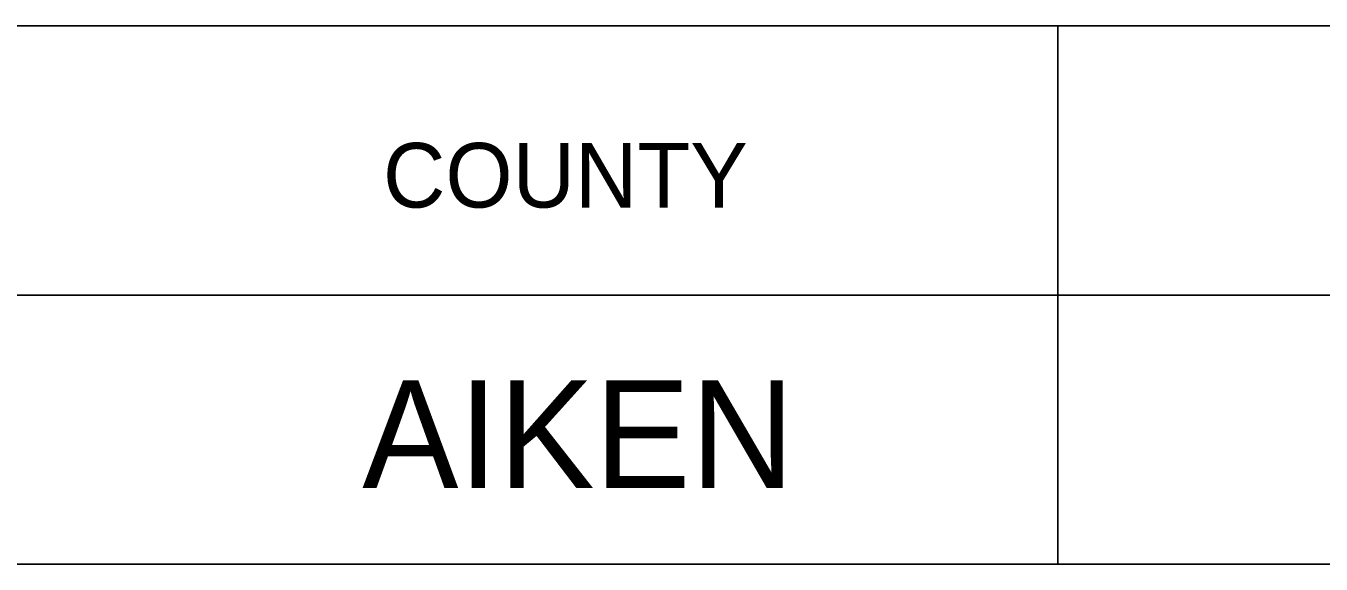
# Model space of a CAD drawing. Extents: x 1000 to 1162, y 999 to 8520.
# Drawn here: x 1139.21 to 1145.22, y 6850.05 to 6852.55 of the extents above; entities that cross this region are included whole.
import ezdxf

# ---------------------------------------------------------------- set-up
doc = ezdxf.new("R2010")
doc.units = 0
doc.layers.add('Level 20', color=7, linetype='Continuous')
doc.layers.add('Level 3', color=7, linetype='Continuous')

msp = doc.modelspace()

# ---------------------------------------------------------------- linework, layer by layer
at = {"layer": 'Level 3'}
for p, q in [((1133.055, 6852.5458), (1161.555, 6852.5458)), ((1133.055, 6852.5458), (1161.555, 6852.5458)), ((1133.055, 6852.5458), (1161.555, 6852.5458)), ((1133.055, 6852.5458), (1161.555, 6852.5458)), ((1133.055, 6852.5458), (1161.555, 6852.5458)), ((1133.055, 6852.5458), (1161.555, 6852.5458)), ((1133.055, 6852.5458), (1161.555, 6852.5458)), ((1133.055, 6852.5458), (1161.555, 6852.5458)), ((1133.055, 6852.5458), (1161.555, 6852.5458)), ((1133.055, 6852.5458), (1161.555, 6852.5458)), ((1133.055, 6852.5458), (1161.555, 6852.5458)), ((1133.055, 6852.5458), (1161.555, 6852.5458)), ((1133.055, 6852.5458), (1161.555, 6852.5458)), ((1133.055, 6852.5458), (1161.555, 6852.5458)), ((1133.055, 6852.5458), (1161.555, 6852.5458)), ((1133.055, 6852.5458), (1161.555, 6852.5458)), ((1133.055, 6852.5458), (1161.555, 6852.5458)), ((1133.055, 6852.5458), (1161.555, 6852.5458)), ((1133.055, 6852.5458), (1161.555, 6852.5458)), ((1133.055, 6852.5458), (1161.555, 6852.5458)), ((1133.055, 6852.5458), (1161.555, 6852.5458)), ((1133.055, 6852.5458), (1161.555, 6852.5458)), ((1133.055, 6852.5458), (1161.555, 6852.5458)), ((1133.055, 6852.5458), (1161.555, 6852.5458)), ((1133.055, 6852.5458), (1161.555, 6852.5458)), ((1133.055, 6852.5458), (1161.555, 6852.5458)), ((1133.055, 6852.5458), (1161.555, 6852.5458)), ((1133.055, 6852.5458), (1161.555, 6852.5458)), ((1133.055, 6852.5458), (1161.555, 6852.5458)), ((1133.055, 6852.5458), (1161.555, 6852.5458)), ((1133.055, 6852.5458), (1161.555, 6852.5458)), ((1133.055, 6852.5458), (1161.555, 6852.5458)), ((1133.055, 6852.5458), (1161.555, 6852.5458)), ((1133.055, 6852.5458), (1161.555, 6852.5458)), ((1133.055, 6852.5458), (1161.555, 6852.5458)), ((1133.055, 6852.5458), (1161.555, 6852.5458)), ((1133.055, 6852.5458), (1161.555, 6852.5458)), ((1133.055, 6852.5458), (1161.555, 6852.5458)), ((1133.055, 6852.5458), (1161.555, 6852.5458)), ((1133.055, 6852.5458), (1161.555, 6852.5458)), ((1133.055, 6852.5458), (1161.555, 6852.5458)), ((1133.055, 6852.5458), (1161.555, 6852.5458)), ((1133.055, 6852.5458), (1161.555, 6852.5458)), ((1133.055, 6852.5458), (1161.555, 6852.5458)), ((1133.055, 6852.5458), (1161.555, 6852.5458)), ((1133.055, 6852.5458), (1161.555, 6852.5458)), ((1133.055, 6852.5458), (1161.555, 6852.5458)), ((1133.055, 6852.5458), (1161.555, 6852.5458)), ((1133.055, 6852.5458), (1161.555, 6852.5458)), ((1143.9997, 6852.5458), (1143.9997, 6850.0458)), ((1143.9997, 6852.5458), (1143.9997, 6850.0458)), ((1143.9997, 6852.5458), (1143.9997, 6850.0458)), ((1143.9997, 6852.5458), (1143.9997, 6850.0458)), ((1143.9997, 6852.5458), (1143.9997, 6850.0458)), ((1143.9997, 6852.5458), (1143.9997, 6850.0458)), ((1143.9997, 6852.5458), (1143.9997, 6850.0458)), ((1143.9997, 6852.5458), (1143.9997, 6850.0458)), ((1143.9997, 6852.5458), (1143.9997, 6850.0458)), ((1143.9997, 6852.5458), (1143.9997, 6850.0458)), ((1143.9997, 6852.5458), (1143.9997, 6850.0458)), ((1143.9997, 6852.5458), (1143.9997, 6850.0458)), ((1143.9997, 6852.5458), (1143.9997, 6850.0458)), ((1143.9997, 6852.5458), (1143.9997, 6850.0458)), ((1143.9997, 6852.5458), (1143.9997, 6850.0458)), ((1143.9997, 6852.5458), (1143.9997, 6850.0458)), ((1143.9997, 6852.5458), (1143.9997, 6850.0458)), ((1143.9997, 6852.5458), (1143.9997, 6850.0458)), ((1143.9997, 6852.5458), (1143.9997, 6850.0458)), ((1143.9997, 6852.5458), (1143.9997, 6850.0458)), ((1143.9997, 6852.5458), (1143.9997, 6850.0458)), ((1143.9997, 6852.5458), (1143.9997, 6850.0458)), ((1143.9997, 6852.5458), (1143.9997, 6850.0458)), ((1143.9997, 6852.5458), (1143.9997, 6850.0458)), ((1143.9997, 6852.5458), (1143.9997, 6850.0458)), ((1143.9997, 6852.5458), (1143.9997, 6850.0458)), ((1143.9997, 6852.5458), (1143.9997, 6850.0458)), ((1143.9997, 6852.5458), (1143.9997, 6850.0458)), ((1143.9997, 6852.5458), (1143.9997, 6850.0458)), ((1143.9997, 6852.5458), (1143.9997, 6850.0458)), ((1143.9997, 6852.5458), (1143.9997, 6850.0458)), ((1143.9997, 6852.5458), (1143.9997, 6850.0458)), ((1143.9997, 6852.5458), (1143.9997, 6850.0458)), ((1143.9997, 6852.5458), (1143.9997, 6850.0458)), ((1143.9997, 6852.5458), (1143.9997, 6850.0458)), ((1143.9997, 6852.5458), (1143.9997, 6850.0458)), ((1143.9997, 6852.5458), (1143.9997, 6850.0458)), ((1143.9997, 6852.5458), (1143.9997, 6850.0458)), ((1143.9997, 6852.5458), (1143.9997, 6850.0458)), ((1143.9997, 6852.5458), (1143.9997, 6850.0458)), ((1143.9997, 6852.5458), (1143.9997, 6850.0458)), ((1143.9997, 6852.5458), (1143.9997, 6850.0458)), ((1143.9997, 6852.5458), (1143.9997, 6850.0458)), ((1143.9997, 6852.5458), (1143.9997, 6850.0458)), ((1143.9997, 6852.5458), (1143.9997, 6850.0458)), ((1143.9997, 6852.5458), (1143.9997, 6850.0458)), ((1143.9997, 6852.5458), (1143.9997, 6850.0458)), ((1143.9997, 6852.5458), (1143.9997, 6850.0458)), ((1143.9997, 6852.5458), (1143.9997, 6850.0458)), ((1133.055, 6851.2958), (1161.555, 6851.2958)), ((1133.055, 6851.2958), (1161.555, 6851.2958)), ((1133.055, 6851.2958), (1161.555, 6851.2958)), ((1133.055, 6851.2958), (1161.555, 6851.2958)), ((1133.055, 6851.2958), (1161.555, 6851.2958)), ((1133.055, 6851.2958), (1161.555, 6851.2958)), ((1133.055, 6851.2958), (1161.555, 6851.2958)), ((1133.055, 6851.2958), (1161.555, 6851.2958)), ((1133.055, 6851.2958), (1161.555, 6851.2958)), ((1133.055, 6851.2958), (1161.555, 6851.2958)), ((1133.055, 6851.2958), (1161.555, 6851.2958)), ((1133.055, 6851.2958), (1161.555, 6851.2958)), ((1133.055, 6851.2958), (1161.555, 6851.2958)), ((1133.055, 6851.2958), (1161.555, 6851.2958)), ((1133.055, 6851.2958), (1161.555, 6851.2958)), ((1133.055, 6851.2958), (1161.555, 6851.2958)), ((1133.055, 6851.2958), (1161.555, 6851.2958)), ((1133.055, 6851.2958), (1161.555, 6851.2958)), ((1133.055, 6851.2958), (1161.555, 6851.2958)), ((1133.055, 6851.2958), (1161.555, 6851.2958)), ((1133.055, 6851.2958), (1161.555, 6851.2958)), ((1133.055, 6851.2958), (1161.555, 6851.2958)), ((1133.055, 6851.2958), (1161.555, 6851.2958)), ((1133.055, 6851.2958), (1161.555, 6851.2958)), ((1133.055, 6851.2958), (1161.555, 6851.2958)), ((1133.055, 6851.2958), (1161.555, 6851.2958)), ((1133.055, 6851.2958), (1161.555, 6851.2958)), ((1133.055, 6851.2958), (1161.555, 6851.2958)), ((1133.055, 6851.2958), (1161.555, 6851.2958)), ((1133.055, 6851.2958), (1161.555, 6851.2958)), ((1133.055, 6851.2958), (1161.555, 6851.2958)), ((1133.055, 6851.2958), (1161.555, 6851.2958)), ((1133.055, 6851.2958), (1161.555, 6851.2958)), ((1133.055, 6851.2958), (1161.555, 6851.2958)), ((1133.055, 6851.2958), (1161.555, 6851.2958)), ((1133.055, 6851.2958), (1161.555, 6851.2958)), ((1133.055, 6851.2958), (1161.555, 6851.2958)), ((1133.055, 6851.2958), (1161.555, 6851.2958)), ((1133.055, 6851.2958), (1161.555, 6851.2958)), ((1133.055, 6851.2958), (1161.555, 6851.2958)), ((1133.055, 6851.2958), (1161.555, 6851.2958)), ((1133.055, 6851.2958), (1161.555, 6851.2958)), ((1133.055, 6851.2958), (1161.555, 6851.2958)), ((1133.055, 6851.2958), (1161.555, 6851.2958)), ((1133.055, 6851.2958), (1161.555, 6851.2958)), ((1133.055, 6851.2958), (1161.555, 6851.2958)), ((1133.055, 6851.2958), (1161.555, 6851.2958)), ((1133.055, 6851.2958), (1161.555, 6851.2958)), ((1133.055, 6851.2958), (1161.555, 6851.2958)), ((1133.055, 6850.0458), (1161.555, 6850.0458)), ((1133.055, 6850.0458), (1161.555, 6850.0458)), ((1133.055, 6850.0458), (1161.555, 6850.0458)), ((1133.055, 6850.0458), (1161.555, 6850.0458)), ((1133.055, 6850.0458), (1161.555, 6850.0458)), ((1133.055, 6850.0458), (1161.555, 6850.0458)), ((1133.055, 6850.0458), (1161.555, 6850.0458)), ((1133.055, 6850.0458), (1161.555, 6850.0458)), ((1133.055, 6850.0458), (1161.555, 6850.0458)), ((1133.055, 6850.0458), (1161.555, 6850.0458)), ((1133.055, 6850.0458), (1161.555, 6850.0458)), ((1133.055, 6850.0458), (1161.555, 6850.0458)), ((1133.055, 6850.0458), (1161.555, 6850.0458)), ((1133.055, 6850.0458), (1161.555, 6850.0458)), ((1133.055, 6850.0458), (1161.555, 6850.0458)), ((1133.055, 6850.0458), (1161.555, 6850.0458)), ((1133.055, 6850.0458), (1161.555, 6850.0458)), ((1133.055, 6850.0458), (1161.555, 6850.0458)), ((1133.055, 6850.0458), (1161.555, 6850.0458)), ((1133.055, 6850.0458), (1161.555, 6850.0458)), ((1133.055, 6850.0458), (1161.555, 6850.0458)), ((1133.055, 6850.0458), (1161.555, 6850.0458)), ((1133.055, 6850.0458), (1161.555, 6850.0458)), ((1133.055, 6850.0458), (1161.555, 6850.0458)), ((1133.055, 6850.0458), (1161.555, 6850.0458)), ((1133.055, 6850.0458), (1161.555, 6850.0458)), ((1133.055, 6850.0458), (1161.555, 6850.0458)), ((1133.055, 6850.0458), (1161.555, 6850.0458)), ((1133.055, 6850.0458), (1161.555, 6850.0458)), ((1133.055, 6850.0458), (1161.555, 6850.0458)), ((1133.055, 6850.0458), (1161.555, 6850.0458)), ((1133.055, 6850.0458), (1161.555, 6850.0458)), ((1133.055, 6850.0458), (1161.555, 6850.0458)), ((1133.055, 6850.0458), (1161.555, 6850.0458)), ((1133.055, 6850.0458), (1161.555, 6850.0458)), ((1133.055, 6850.0458), (1161.555, 6850.0458)), ((1133.055, 6850.0458), (1161.555, 6850.0458)), ((1133.055, 6850.0458), (1161.555, 6850.0458)), ((1133.055, 6850.0458), (1161.555, 6850.0458)), ((1133.055, 6850.0458), (1161.555, 6850.0458)), ((1133.055, 6850.0458), (1161.555, 6850.0458)), ((1133.055, 6850.0458), (1161.555, 6850.0458)), ((1133.055, 6850.0458), (1161.555, 6850.0458)), ((1133.055, 6850.0458), (1161.555, 6850.0458)), ((1133.055, 6850.0458), (1161.555, 6850.0458)), ((1133.055, 6850.0458), (1161.555, 6850.0458)), ((1133.055, 6850.0458), (1161.555, 6850.0458)), ((1133.055, 6850.0458), (1161.555, 6850.0458)), ((1133.055, 6850.0458), (1161.555, 6850.0458))]:
    msp.add_line(p, q, dxfattribs=at)

# ---------------------------------------------------------------- texts
at = {"layer": 'Level 20'}
msp.add_text('AIKEN', height=0.5, dxfattribs=at).set_placement((1140.7706, 6850.4))
at = {"layer": 'Level 3'}
msp.add_text('COUNTY', height=0.3, dxfattribs=at).set_placement((1140.8665, 6851.7021))
msp.add_text('COUNTY', height=0.3, dxfattribs=at).set_placement((1140.8665, 6851.7021))
msp.add_text('COUNTY', height=0.3, dxfattribs=at).set_placement((1140.8665, 6851.7021))
msp.add_text('COUNTY', height=0.3, dxfattribs=at).set_placement((1140.8665, 6851.7021))
msp.add_text('COUNTY', height=0.3, dxfattribs=at).set_placement((1140.8665, 6851.7021))
msp.add_text('COUNTY', height=0.3, dxfattribs=at).set_placement((1140.8665, 6851.7021))
msp.add_text('COUNTY', height=0.3, dxfattribs=at).set_placement((1140.8665, 6851.7021))
msp.add_text('COUNTY', height=0.3, dxfattribs=at).set_placement((1140.8665, 6851.7021))
msp.add_text('COUNTY', height=0.3, dxfattribs=at).set_placement((1140.8665, 6851.7021))
msp.add_text('COUNTY', height=0.3, dxfattribs=at).set_placement((1140.8665, 6851.7021))
msp.add_text('COUNTY', height=0.3, dxfattribs=at).set_placement((1140.8665, 6851.7021))
msp.add_text('COUNTY', height=0.3, dxfattribs=at).set_placement((1140.8665, 6851.7021))
msp.add_text('COUNTY', height=0.3, dxfattribs=at).set_placement((1140.8665, 6851.7021))
msp.add_text('COUNTY', height=0.3, dxfattribs=at).set_placement((1140.8665, 6851.7021))
msp.add_text('COUNTY', height=0.3, dxfattribs=at).set_placement((1140.8665, 6851.7021))
msp.add_text('COUNTY', height=0.3, dxfattribs=at).set_placement((1140.8665, 6851.7021))
msp.add_text('COUNTY', height=0.3, dxfattribs=at).set_placement((1140.8665, 6851.7021))
msp.add_text('COUNTY', height=0.3, dxfattribs=at).set_placement((1140.8665, 6851.7021))
msp.add_text('COUNTY', height=0.3, dxfattribs=at).set_placement((1140.8665, 6851.7021))
msp.add_text('COUNTY', height=0.3, dxfattribs=at).set_placement((1140.8665, 6851.7021))
msp.add_text('COUNTY', height=0.3, dxfattribs=at).set_placement((1140.8665, 6851.7021))
msp.add_text('COUNTY', height=0.3, dxfattribs=at).set_placement((1140.8665, 6851.7021))
msp.add_text('COUNTY', height=0.3, dxfattribs=at).set_placement((1140.8665, 6851.7021))
msp.add_text('COUNTY', height=0.3, dxfattribs=at).set_placement((1140.8665, 6851.7021))
msp.add_text('COUNTY', height=0.3, dxfattribs=at).set_placement((1140.8665, 6851.7021))
msp.add_text('COUNTY', height=0.3, dxfattribs=at).set_placement((1140.8665, 6851.7021))
msp.add_text('COUNTY', height=0.3, dxfattribs=at).set_placement((1140.8665, 6851.7021))
msp.add_text('COUNTY', height=0.3, dxfattribs=at).set_placement((1140.8665, 6851.7021))
msp.add_text('COUNTY', height=0.3, dxfattribs=at).set_placement((1140.8665, 6851.7021))
msp.add_text('COUNTY', height=0.3, dxfattribs=at).set_placement((1140.8665, 6851.7021))
msp.add_text('COUNTY', height=0.3, dxfattribs=at).set_placement((1140.8665, 6851.7021))
msp.add_text('COUNTY', height=0.3, dxfattribs=at).set_placement((1140.8665, 6851.7021))
msp.add_text('COUNTY', height=0.3, dxfattribs=at).set_placement((1140.8665, 6851.7021))
msp.add_text('COUNTY', height=0.3, dxfattribs=at).set_placement((1140.8665, 6851.7021))
msp.add_text('COUNTY', height=0.3, dxfattribs=at).set_placement((1140.8665, 6851.7021))
msp.add_text('COUNTY', height=0.3, dxfattribs=at).set_placement((1140.8665, 6851.7021))
msp.add_text('COUNTY', height=0.3, dxfattribs=at).set_placement((1140.8665, 6851.7021))
msp.add_text('COUNTY', height=0.3, dxfattribs=at).set_placement((1140.8665, 6851.7021))
msp.add_text('COUNTY', height=0.3, dxfattribs=at).set_placement((1140.8665, 6851.7021))
msp.add_text('COUNTY', height=0.3, dxfattribs=at).set_placement((1140.8665, 6851.7021))
msp.add_text('COUNTY', height=0.3, dxfattribs=at).set_placement((1140.8665, 6851.7021))
msp.add_text('COUNTY', height=0.3, dxfattribs=at).set_placement((1140.8665, 6851.7021))
msp.add_text('COUNTY', height=0.3, dxfattribs=at).set_placement((1140.8665, 6851.7021))
msp.add_text('COUNTY', height=0.3, dxfattribs=at).set_placement((1140.8665, 6851.7021))
msp.add_text('COUNTY', height=0.3, dxfattribs=at).set_placement((1140.8665, 6851.7021))
msp.add_text('COUNTY', height=0.3, dxfattribs=at).set_placement((1140.8665, 6851.7021))
msp.add_text('COUNTY', height=0.3, dxfattribs=at).set_placement((1140.8665, 6851.7021))
msp.add_text('COUNTY', height=0.3, dxfattribs=at).set_placement((1140.8665, 6851.7021))
msp.add_text('COUNTY', height=0.3, dxfattribs=at).set_placement((1140.8665, 6851.7021))

doc.saveas('drawing.dxf')
